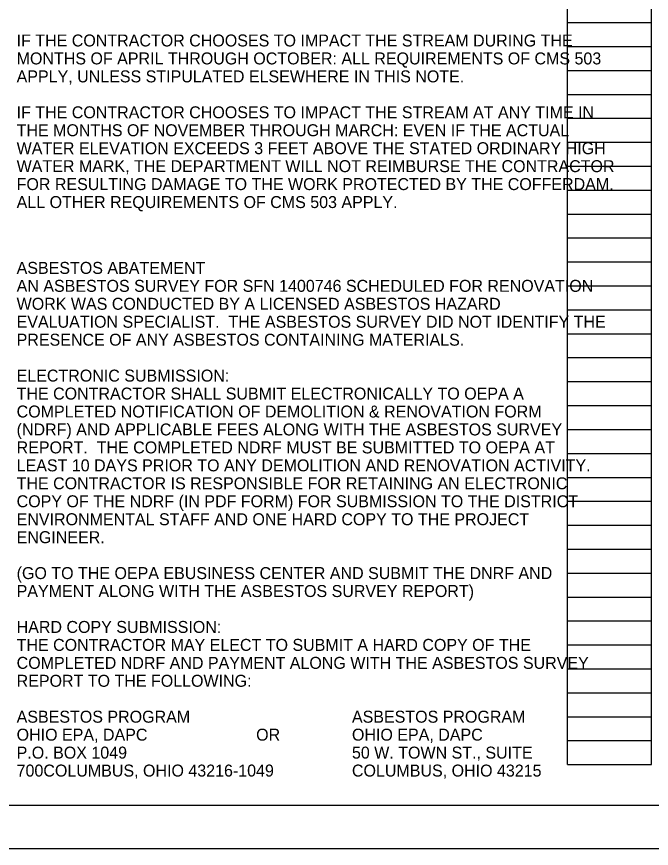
# Model space of a CAD drawing. Extents: x 0 to 34, y 0 to 22.
# Drawn here: x 17.24 to 24.66, y 0 to 9.73 of the extents above; entities that cross this region are included whole.
import ezdxf

# ---------------------------------------------------------------- set-up
doc = ezdxf.new("R2010")
doc.units = 0
for name, color, linetype in [('BR_P_Gen_Text', 7, 'Continuous'), ('SC_Scratch5', 7, 'Continuous'), ('SH_Border', 7, 'Continuous'), ('SH_Cut_Line', 7, 'Continuous'), ('SH_Text', 7, 'Continuous')]:
    doc.layers.add(name, color=color, linetype=linetype)

msp = doc.modelspace()

# ---------------------------------------------------------------- linework, layer by layer
at = {"layer": 'SC_Scratch5'}
for p, q in [((23.68, 0.98), (23.68, 21.14)), ((24.66, 0.98), (24.66, 21.14)), ((23.68, 9.66), (24.66, 9.66)), ((23.68, 9.38), (24.66, 9.38)), ((23.68, 9.1), (24.66, 9.1)), ((23.68, 8.82), (24.66, 8.82)), ((23.68, 8.54), (24.66, 8.54)), ((23.68, 8.26), (24.66, 8.26)), ((23.68, 7.98), (24.66, 7.98)), ((23.68, 7.7), (24.66, 7.7)), ((23.68, 7.42), (24.66, 7.42)), ((23.68, 7.14), (24.66, 7.14)), ((23.68, 6.86), (24.66, 6.86)), ((23.68, 6.58), (24.66, 6.58)), ((23.68, 6.3), (24.66, 6.3)), ((23.68, 6.02), (24.66, 6.02)), ((23.68, 5.74), (24.66, 5.74)), ((23.68, 5.46), (24.66, 5.46)), ((23.68, 5.18), (24.66, 5.18)), ((23.68, 4.9), (24.66, 4.9)), ((23.68, 4.62), (24.66, 4.62)), ((23.68, 4.34), (24.66, 4.34)), ((23.68, 4.06), (24.66, 4.06)), ((23.68, 3.78), (24.66, 3.78)), ((23.68, 3.5), (24.66, 3.5)), ((23.68, 3.22), (24.66, 3.22)), ((23.68, 2.94), (24.66, 2.94)), ((23.68, 2.66), (24.66, 2.66)), ((23.68, 2.38), (24.66, 2.38)), ((23.68, 2.1), (24.66, 2.1)), ((23.68, 1.82), (24.66, 1.82)), ((23.68, 1.54), (24.66, 1.54)), ((23.68, 1.26), (24.66, 1.26)), ((23.68, 0.98), (24.66, 0.98))]:
    msp.add_line(p, q, dxfattribs=at)
at = {"layer": 'SH_Border'}
msp.add_lwpolyline([(1.5, 21.5), (33.5, 21.5), (33.5, 0.5), (1.5, 0.5)], close=True, dxfattribs=at)
at = {"layer": 'SH_Cut_Line'}
msp.add_lwpolyline([(0, 0), (34, 0), (34, 22), (0, 22)], close=True, dxfattribs=at)

# ---------------------------------------------------------------- texts
at = {"layer": 'BR_P_Gen_Text'}
for s, p in [('ASBESTOS ABATEMENT', (17.24, 6.72)), ('AN ASBESTOS SURVEY FOR SFN 1400746 SCHEDULED FOR RENOVATION ', (17.24, 6.51)), ('WORK WAS CONDUCTED BY A LICENSED ASBESTOS HAZARD ', (17.24, 6.3)), ('EVALUATION SPECIALIST.  THE ASBESTOS SURVEY DID NOT IDENTIFY THE ', (17.24, 6.09)), ('PRESENCE OF ANY ASBESTOS CONTAINING MATERIALS.', (17.24, 5.88)), ('ELECTRONIC SUBMISSION:  ', (17.24, 5.46)), ('THE CONTRACTOR SHALL SUBMIT ELECTRONICALLY TO OEPA A ', (17.24, 5.25)), ('COMPLETED NOTIFICATION OF DEMOLITION & RENOVATION FORM ', (17.24, 5.04)), ('(NDRF) AND APPLICABLE FEES ALONG WITH THE ASBESTOS SURVEY ', (17.24, 4.83)), ('REPORT.  THE COMPLETED NDRF MUST BE SUBMITTED TO OEPA AT ', (17.24, 4.62)), ('LEAST 10 DAYS PRIOR TO ANY DEMOLITION AND RENOVATION ACTIVITY. ', (17.24, 4.41)), ('THE CONTRACTOR IS RESPONSIBLE FOR RETAINING AN ELECTRONIC ', (17.24, 4.2)), ('COPY OF THE NDRF (IN PDF FORM) FOR SUBMISSION TO THE DISTRICT ', (17.24, 3.99)), ('ENVIRONMENTAL STAFF AND ONE HARD COPY TO THE PROJECT ', (17.24, 3.78)), ('ENGINEER.   ', (17.24, 3.57)), ('(GO TO THE OEPA EBUSINESS CENTER AND SUBMIT THE DNRF AND ', (17.24, 3.15)), ('PAYMENT ALONG WITH THE ASBESTOS SURVEY REPORT)', (17.24, 2.94)), ('HARD COPY SUBMISSION:', (17.24, 2.52)), ('THE CONTRACTOR MAY ELECT TO SUBMIT A HARD COPY OF THE ', (17.24, 2.31)), ('COMPLETED NDRF AND PAYMENT ALONG WITH THE ASBESTOS SURVEY ', (17.24, 2.1)), ('REPORT TO THE FOLLOWING:', (17.24, 1.89)), ('ASBESTOS PROGRAM', (17.24, 1.47)), ('ASBESTOS PROGRAM', (21.16, 1.47)), ('OHIO EPA, DAPC', (17.24, 1.26)), ('OR', (20.04, 1.26)), ('OHIO EPA, DAPC', (21.16, 1.26)), ('P.O. BOX 1049', (17.24, 1.05)), ('50 W. TOWN ST., SUITE ', (21.16, 1.05)), ('700COLUMBUS, OHIO 43216-1049', (17.24, 0.84)), ('COLUMBUS, OHIO 43215', (21.16, 0.84))]:
    msp.add_text(s, height=0.14, dxfattribs=at).set_placement(p)
at = {"layer": 'SH_Text'}
for s, p in [('IF THE CONTRACTOR CHOOSES TO IMPACT THE STREAM DURING THE ', (17.24, 9.38)), ('MONTHS OF APRIL THROUGH OCTOBER: ALL REQUIREMENTS OF CMS 503 ', (17.24, 9.17)), ('APPLY, UNLESS STIPULATED ELSEWHERE IN THIS NOTE.', (17.24, 8.96)), ('IF THE CONTRACTOR CHOOSES TO IMPACT THE STREAM AT ANY TIME IN ', (17.24, 8.54)), ('THE MONTHS OF NOVEMBER THROUGH MARCH: EVEN IF THE ACTUAL ', (17.24, 8.33)), ('WATER ELEVATION EXCEEDS 3 FEET ABOVE THE STATED ORDINARY HIGH ', (17.24, 8.12)), ('WATER MARK, THE DEPARTMENT WILL NOT REIMBURSE THE CONTRACTOR ', (17.24, 7.91)), ('FOR RESULTING DAMAGE TO THE WORK PROTECTED BY THE COFFERDAM. ', (17.24, 7.7)), ('ALL OTHER REQUIREMENTS OF CMS 503 APPLY.', (17.24, 7.49))]:
    msp.add_text(s, height=0.14, dxfattribs=at).set_placement(p)

doc.saveas('drawing.dxf')
